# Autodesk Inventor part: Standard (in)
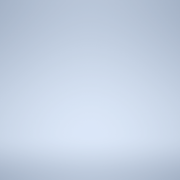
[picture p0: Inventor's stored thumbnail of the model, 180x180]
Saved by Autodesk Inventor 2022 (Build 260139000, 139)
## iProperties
Shininess: 64.0
Length Units: 11272
Angle Units: 11279
Time Units: 11290
Mass Units: 11286
Length Display Precision: 3
Angle Display Precision: 2
Compacted: True
Part Number: Standard (in)
Document SubType Name: Modeling
Created: 2002-08
Density: 1 g/cm^3
Material: Generico
Appearance: Default
Density: 0.0
Volumn: 0.0
Area: 0.0
PropertySet Name: Model Information
Control State: 0
Master: False
Checked Out: False
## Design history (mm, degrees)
